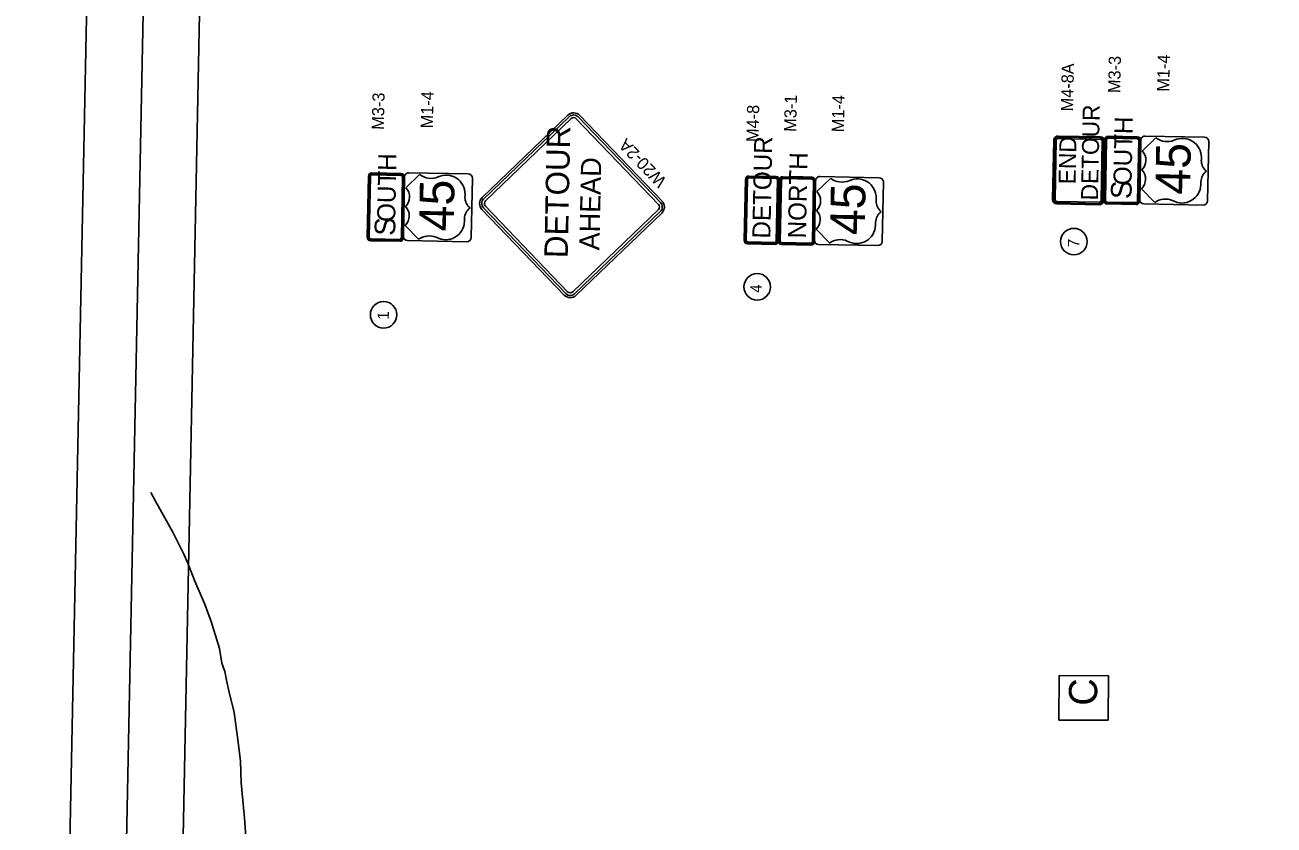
# Model space of a CAD drawing. Extents: x 335726 to 369746, y 119154 to 200788.
# Drawn here: x 335726 to 352294, y 149591 to 160200 of the extents above; entities that cross this region are included whole.
import ezdxf

# ---------------------------------------------------------------- set-up
doc = ezdxf.new("R2010")
doc.units = 0
for name, color, linetype in [('CA-TEXT', 7, 'Continuous'), ('Level 1', 7, 'Continuous'), ('P_RDWY_Text', 7, 'Continuous'), ('P_SGN_Cell', 7, 'Continuous'), ('PLT_Sheet_Border', 7, 'Continuous'), ('PLT_Sheet_Info', 7, 'Continuous')]:
    doc.layers.add(name, color=color, linetype=linetype)

msp = doc.modelspace()

# ---------------------------------------------------------------- linework, layer by layer
at = {"layer": 'CA-TEXT'}
msp.add_line((349761, 151288), (349761, 151288), dxfattribs=at)
msp.add_lwpolyline([(350096, 150980), (349440, 150983), (349442, 151572), (350099, 151569)], close=True, dxfattribs=at)
for centre in [(349639, 157327), (345439, 156727), (340483, 156357)]:
    msp.add_circle(centre, 176, dxfattribs=at)
at = {"layer": 'Level 1'}
for points in [[(337888, 153065), (337834, 153181), (337686, 153476), (337458, 153884), (337394, 154000)], [(338339, 151739), (338304, 151933), (338194, 152290), (338109, 152528), (337980, 152823), (337888, 153065)], [(338543, 150754), (338502, 151081), (338430, 151369), (338400, 151513), (338376, 151626), (338339, 151739)], [(338749, 148053), (338695, 148954), (338672, 149198), (338639, 149680), (338594, 150149), (338584, 150443), (338543, 150754)]]:
    msp.add_lwpolyline(points, dxfattribs=at)
at = {"layer": 'P_RDWY_Text'}
msp.add_lwpolyline([(335726, 119818), (336753, 170808), (369746, 170144), (368719, 119154)], close=True, dxfattribs=at)
at = {"layer": 'P_SGN_Cell'}
for p, q in [((349993, 158716), (349430, 158727)), ((350094, 158726), (350484, 158718)), ((350585, 158727), (351373, 158711)), ((349357, 157885), (349373, 158672)), ((349371, 157885), (349387, 158672)), ((349390, 157884), (349406, 158672)), ((349992, 158702), (349430, 158713)), ((349992, 158683), (349430, 158695)), ((349999, 157872), (350015, 158659)), ((350018, 157872), (350034, 158659)), ((350032, 157871), (350048, 158682)), ((350032, 157871), (350048, 158659)), ((350043, 157872), (350059, 158682)), ((350058, 157871), (350074, 158681)), ((350094, 158715), (350484, 158707)), ((350094, 158700), (350483, 158692)), ((350502, 158673), (350485, 157863)), ((350517, 158672), (350500, 157863)), ((350528, 158672), (350512, 157862)), ((350512, 157885), (350528, 158672)), ((350728, 158703), (350546, 158528)), ((351428, 158654), (351420, 158260)), ((351428, 158654), (351428, 158654)), ((351330, 158405), (351330, 158441)), ((340326, 158228), (340716, 158220)), ((340327, 158239), (340717, 158231)), ((340818, 158240), (341605, 158224)), ((351420, 158260), (351412, 157867)), ((340264, 157384), (340281, 158195)), ((340276, 157385), (340292, 158194)), ((340291, 157384), (340307, 158194)), ((340326, 158213), (340716, 158205)), ((340734, 158186), (340718, 157376)), ((340749, 158185), (340733, 157375)), ((340761, 158185), (340744, 157375)), ((340745, 157398), (340761, 158185)), ((340961, 158216), (340779, 158041)), ((341660, 158167), (341652, 157773)), ((341660, 158167), (341660, 158167)), ((345717, 157334), (345733, 158144)), ((345728, 157334), (345745, 158144)), ((345743, 157334), (345760, 158144)), ((345779, 158188), (346169, 158180)), ((345779, 158177), (346169, 158169)), ((345779, 158162), (346169, 158154)), ((346187, 158135), (346171, 157325)), ((346202, 158135), (346186, 157325)), ((346197, 157348), (346213, 158135)), ((346213, 158135), (346197, 157325)), ((346413, 158166), (346231, 157991)), ((346271, 158190), (347058, 158174)), ((347113, 158117), (347105, 157723)), ((347113, 158117), (347113, 158117)), ((351323, 158084), (351324, 158119)), ((341562, 157918), (341563, 157954)), ((347015, 157868), (347015, 157904)), ((350536, 158028), (350711, 157846)), ((341652, 157773), (341645, 157380)), ((349975, 157830), (349412, 157842)), ((349974, 157816), (349412, 157828)), ((349975, 157849), (349413, 157860)), ((350076, 157852), (350466, 157844)), ((350076, 157837), (350466, 157829)), ((350076, 157826), (350466, 157818)), ((351355, 157812), (350567, 157827)), ((341556, 157597), (341556, 157632)), ((347008, 157546), (347009, 157582)), ((347105, 157723), (347097, 157329)), ((340769, 157541), (340944, 157359)), ((346221, 157491), (346396, 157309)), ((340308, 157339), (340698, 157331)), ((340309, 157365), (340699, 157357)), ((340309, 157350), (340699, 157342)), ((341587, 157324), (340800, 157340)), ((345761, 157300), (346151, 157292)), ((345761, 157289), (346151, 157281)), ((345762, 157315), (346152, 157307)), ((347040, 157274), (346252, 157290))]:
    msp.add_line(p, q, dxfattribs=at)
for points in [[(342926, 159004), (341790, 157913)], [(342946, 158983), (341810, 157892)], [(342970, 158958), (341835, 157866)], [(344129, 157821), (343038, 158957)], [(344155, 157846), (343064, 158981)], [(344175, 157866), (343085, 159001)], [(345283, 158153), (345267, 157343)], [(345295, 158153), (345278, 157343)], [(345310, 158152), (345293, 157343)], [(345689, 158190), (345329, 158197)], [(345689, 158179), (345329, 158186)], [(345689, 158164), (345329, 158171)], [(345691, 157335), (345707, 158144)], [(345706, 157334), (345722, 158144)], [(345717, 157334), (345733, 158144)], [(341787, 157754), (342878, 156618)], [(341807, 157774), (342899, 156638)], [(341833, 157798), (342924, 156662)], [(342992, 156661), (344128, 157752)], [(343017, 156635), (344153, 157726)], [(343037, 156615), (344173, 157706)], [(345311, 157309), (345671, 157301)], [(345311, 157297), (345671, 157290)], [(345312, 157324), (345672, 157316)]]:
    msp.add_lwpolyline(points, dxfattribs=at)
for centre, radius, start, end in [((343004, 158923), 112, 43.8468, 133.8468), ((343004, 158923), 83.9, 43.8468, 133.8468), ((343004, 158923), 48.2, 43.8468, 133.8468), ((349429, 158671), 56.2, 88.8468, 178.8468), ((350093, 158681), 45, 88.8462, 178.8462), ((350584, 158671), 56.2, 88.8462, 178.8462), ((349429, 158671), 42.2, 88.8468, 178.8468), ((349429, 158671), 23.4, 88.8468, 178.8468), ((349991, 158660), 42.2, 358.8468, 88.8468), ((349991, 158660), 23.4, 358.8468, 88.8468), ((349991, 158660), 56.2, 358.8468, 88.8468), ((350093, 158681), 33.7, 88.8462, 178.8462), ((350093, 158681), 18.7, 88.8462, 178.8462), ((350483, 158673), 18.7, 358.8462, 88.8462), ((350483, 158673), 45, 358.8462, 88.8462), ((350483, 158673), 33.7, 358.8462, 88.8462), ((350878, 158903), 250, 233.1143, 291.9873), ((351080, 158446), 250, 358.8462, 115.6928), ((351372, 158655), 56.2, 358.8462, 88.8462), ((350416, 158406), 179, 314.4191, 43.2734), ((351510, 158403), 181, 179.1885, 231.634), ((340326, 158194), 45, 88.8462, 178.8462), ((340326, 158194), 33.7, 88.8462, 178.8462), ((340716, 158186), 45, 358.8462, 88.8462), ((340817, 158184), 56.2, 88.8462, 178.8462), ((350411, 158156), 179, 314.4191, 43.2734), ((351505, 158115), 181, 126.0584, 178.5039), ((340326, 158194), 18.7, 88.8462, 178.8462), ((340716, 158186), 33.7, 358.8462, 88.8462), ((340716, 158186), 18.7, 358.8462, 88.8462), ((341111, 158416), 250, 233.1143, 291.9873), ((341313, 157959), 250, 358.8462, 115.6928), ((341604, 158168), 56.2, 358.8462, 88.8462), ((345328, 158152), 45, 88.8468, 178.8468), ((345328, 158152), 33.7, 88.8468, 178.8468), ((345328, 158152), 18.7, 88.8468, 178.8468), ((345688, 158145), 45, 358.8468, 88.8468), ((345688, 158145), 33.7, 358.8468, 88.8468), ((345688, 158145), 18.7, 358.8468, 88.8468), ((345778, 158143), 45, 88.8462, 178.8462), ((345778, 158143), 33.7, 88.8462, 178.8462), ((345778, 158143), 18.7, 88.8462, 178.8462), ((346168, 158135), 45, 358.8462, 88.8462), ((346168, 158135), 33.7, 358.8462, 88.8462), ((346168, 158135), 18.7, 358.8462, 88.8462), ((346269, 158134), 56.2, 88.8462, 178.8462), ((346564, 158366), 250, 233.1143, 291.9873), ((346766, 157909), 250, 358.8462, 115.6928), ((347057, 158118), 56.2, 358.8462, 88.8462), ((351073, 158089), 250, 240.0981, 358.8463), ((340649, 157918), 179, 314.4191, 43.2734), ((341743, 157915), 181, 179.1885, 231.634), ((341868, 157832), 112, 133.8449, 223.8468), ((346101, 157868), 179, 314.4191, 43.2734), ((340644, 157669), 179, 314.4191, 43.2734), ((341737, 157628), 181, 126.0584, 178.5039), ((341868, 157832), 83.9, 133.8449, 223.8468), ((341868, 157832), 48.2, 133.8449, 223.8468), ((344095, 157787), 48.2, 313.854, 44.4977), ((344095, 157787), 83.9, 313.854, 44.4977), ((344095, 157787), 112, 313.854, 44.4977), ((346096, 157618), 179, 314.4191, 43.2734), ((347196, 157865), 181, 179.1885, 231.634), ((349413, 157884), 56.2, 178.8468, 268.8468), ((349413, 157884), 42.2, 178.8468, 268.8468), ((349413, 157884), 23.4, 178.8468, 268.8468), ((349413, 157884), 23.4, 178.8468, 187.6911), ((349976, 157873), 56.2, 268.8468, 358.8468), ((349976, 157873), 42.2, 268.8468, 358.8468), ((349976, 157873), 23.4, 268.8468, 358.8468), ((350077, 157871), 45, 179.6119, 268.8462), ((350077, 157871), 33.7, 178.8462, 268.8462), ((350077, 157871), 18.7, 178.8462, 268.8462), ((350467, 157863), 33.7, 268.8462, 358.8462), ((350467, 157863), 18.7, 268.8462, 358.8462), ((350467, 157863), 45, 268.8462, 358.8462), ((350568, 157884), 56.2, 178.8462, 268.8462), ((350854, 157641), 250, 67.7159, 124.7982), ((351356, 157868), 56.2, 268.8462, 358.8462), ((341306, 157602), 250, 240.0981, 358.8463), ((347190, 157577), 181, 126.0584, 178.5039), ((341086, 157153), 250, 67.7159, 124.7982), ((346758, 157551), 250, 240.0981, 358.8463), ((340309, 157384), 45, 179.6119, 268.8462), ((340309, 157384), 33.7, 178.8462, 268.8462), ((340309, 157384), 18.7, 178.8462, 268.8462), ((340699, 157376), 45, 268.8462, 358.8462), ((340699, 157376), 18.7, 268.8462, 358.8462), ((340699, 157376), 33.7, 268.8462, 358.8462), ((340801, 157397), 56.2, 178.8462, 268.8462), ((341588, 157381), 56.2, 268.8462, 358.8462), ((345312, 157342), 45, 178.8468, 268.8468), ((345312, 157342), 33.7, 178.8468, 268.8468), ((345312, 157342), 18.7, 178.8468, 268.8468), ((345312, 157342), 18.7, 178.8468, 186.1883), ((345672, 157335), 45, 268.8468, 358.8468), ((345672, 157335), 33.7, 268.8468, 358.8468), ((345672, 157335), 18.7, 268.8468, 358.8468), ((345762, 157334), 45, 179.6119, 268.8462), ((345762, 157334), 33.7, 178.8462, 268.8462), ((345762, 157334), 18.7, 178.8462, 268.8462), ((346152, 157326), 33.7, 268.8462, 358.8462), ((346152, 157326), 45, 268.8462, 358.8462), ((346152, 157326), 18.7, 268.8462, 358.8462), ((346254, 157346), 56.2, 178.8462, 268.8462), ((346539, 157103), 250, 67.7159, 124.7982), ((347041, 157331), 56.2, 268.8462, 358.8462), ((342959, 156696), 112, 223.8468, 313.8468), ((342959, 156696), 83.9, 223.8468, 313.8468), ((342959, 156696), 48.2, 223.8468, 313.8468)]:
    msp.add_arc(centre, radius, start, end, dxfattribs=at)
at = {"layer": 'PLT_Sheet_Border'}
for points in [[(368719, 119154), (369746, 170144), (336753, 170808), (335726, 119818)], [(367976, 119529), (368976, 169169), (337483, 169803), (336483, 120163)]]:
    msp.add_lwpolyline(points, close=True, dxfattribs=at)
at = {"layer": 'PLT_Sheet_Info'}
msp.add_line((337264, 121685), (338215, 168926), dxfattribs=at)

# ---------------------------------------------------------------- texts
at = {"layer": 'CA-TEXT'}
for s, height, rotation, p in [('7', 150, 88.8468, (349709, 157251)), ('4', 150, 88.8468, (345497, 156647)), ('1', 150, 88.8468, (340551, 156290)), ('C', 375, 89.767, (349948, 151173))]:
    msp.add_text(s, height=height, rotation=rotation, dxfattribs=at).set_placement(p)
at = {"layer": 'P_SGN_Cell'}
for s, height, rotation, p in [('M3-3', 162, 88.8462, (350254, 159295)), ('M1-4', 162, 88.8462, (350903, 159314)), ('M4-8A', 162, 88.8468, (349628, 159052)), ('M3-3', 162, 88.8462, (340487, 158808)), ('M1-4', 162, 88.8462, (341136, 158827)), ('M3-1', 162, 88.8462, (345956, 158781)), ('M1-4', 162, 88.8462, (346589, 158776)), ('M4-8', 162, 88.8468, (345456, 158646)), ('DETOUR', 225, 88.8468, (349958, 157872)), ('OUTH', 240, 88.8462, (350403, 158073)), ('DETOUR', 310.7, 88.8468, (342925, 157106)), ('W20-2A', 162, 133.8468, (344247, 158141)), ('DETOUR', 240, 88.8468, (345613, 157366)), ('END', 225, 88.8468, (349661, 158086)), ('45', 460, 88.8462, (351178, 157947)), ('OUTH', 240, 88.8462, (340636, 157586)), ('AHEAD', 267.9, 88.8468, (343346, 157209)), ('NORTH', 240, 88.8462, (346085, 157368)), ('45', 460, 88.8462, (341411, 157460)), ('45', 460, 88.8462, (346863, 157410)), ('S', 274, 88.8462, (350403, 157889)), ('S', 274, 88.8462, (340636, 157402))]:
    msp.add_text(s, height=height, rotation=rotation, dxfattribs=at).set_placement(p)

doc.saveas('drawing.dxf')
